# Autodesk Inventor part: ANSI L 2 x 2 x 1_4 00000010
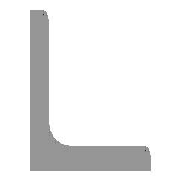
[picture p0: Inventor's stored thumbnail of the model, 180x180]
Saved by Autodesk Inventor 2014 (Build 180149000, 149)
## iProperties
_FrameMemberDoc: Frame Member File
_Version: 15.0.0
_CCFamilyMember: 11
_CCFamilyDisplayName: ANSI L (Equal angles) - Angle Steel
Created: 2007-02
Part Number: ANSI L 2 x 2 x 1_4 00000010
Material: Steel, Mild
Document SubType Name: Modeling
Standard: AISC
Designer: Autodesk, Inc.
Size Designation: L 2 x 2 x 1/4
Stock Number: L 2 x 2 x 1/4
Density: 7.86 g/cm^3
Description: Angle Steel
Standards Organization: ANSI
Language: en-US
Categories: <MemberInstance><Categories><Category DisplayName="Structural Shapes" InternalName="089c4875-fa83-4c05-b084-43b9cc11f5ed" Mnemonic="GRDR"><CategoryParameter Dis
Mass: 5445.94 g
Surface Area: 2281.31 cm^2
Volume: 692.867 cm^3
Appearance: Steel
IsCustomPart: 1
G_L: 47.162 in
G_W: 2.000 in
G_H: 2.000 in
+2283D808-2F1C-4F88-8374-570C52666FBE+CUTDETAIL1: Notch
+7C29D4AB-C23D-49FB-A867-DF174C4492B2+CUTDETAIL2: Cut
+B5C2A3DA-737D-4151-A737-5317CCD108A8+CUTDETAIL3: Notch
+B0BDC58B-F2D9-4CD2-9A0D-96DA2DAF80EC+CUTDETAIL4: Notch
+B47E5654-80DF-4891-BFA1-6A0897AAD3E9+CUTDETAIL5: Notch
Author: Autodesk, Inc.
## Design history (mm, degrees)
node "Start plane"
node "End plane"
sketch "Sketch"
  geometry: L1 (50.8, 0)-(0, 0); L2 (0, 0)-(0, 50.8); L3 (0, 50.8)-(3.302, 50.8); L4 (6.35, 47.752)-(6.35, 12.7); L5 (12.7, 6.35)-(47.752, 6.35); L6 (50.8, 3.302)-(50.8, 0); L7 (0, -11.041)-(0, 31.538); L8 (-11.041, 0)-(31.538, 0); L9 (0, 63.926)-(0, -23.536) reference; L10 (-23.536, 0)-(63.926, 0) reference; A1 r 6.35 centre (12.7, 12.7) between (6.35, 12.7) and (12.7, 6.35); A2 r 3.048 centre (3.302, 47.752) between (6.35, 47.752) and (3.302, 50.8); A3 r 3.048 centre (47.752, 3.302) between (50.8, 3.302) and (47.752, 6.35); 3 further points
  constraints: 16 end point, 6 point on circle, 6 point on line, 6 tangent, 4 parallel, 3 centre point, 2 collinear, 1 equal radius, 1 horizontal, 1 perpendicular
  dimensions: "d0" = 50.8 distance between parallel lines of L6 L2 (= G_H); "d1" = 50.8 distance between parallel lines of L3 L1 (= G_H); "d2" = 6.35 distance between parallel lines of L2 L4 (= G_T); "d3" = 6.35 distance between parallel lines of L1 L5 (= G_T); "d10" = 0 distance between parallel lines of L7 L2 (computed from ex); "d11" = 0 distance between parallel lines of L8 L1 (computed from d10); "d14" = 6.35 radius of A1 (= G_IR); "d15" = 3.048 radius of A2 (= G_ER)
extrude "Body" new body sketch "Sketch" stored distance "d4" = 1197.9024 (= G_L); taper "d5" = 0 deg
node "Driven Length"
  sketch "Sketch7"
    geometry: L1 (0, 0)-(10, 0) reference
    constraints: 2 end point, 1 horizontal
  workplane "Work Plane12"
  sketch "Sketch8"
    geometry: L1 (-2, 0)-(12, 0) reference; L2 (-2, 1197.902)-(12, 1197.902) reference
    dimensions: "d25" = 1197.9024 distance between parallel lines of L1 L2 (derived)
workplane "Work Plane3"
workplane "Work Plane4"
workplane "Work Plane5"
split "Split1"
workplane "Work Plane6"
workplane "Work Plane7"
workplane "Work Plane8"
workplane "Work Plane9"
workplane "Work Plane10"
workplane "Work Plane11"
workplane "Work Plane13"
workplane "Work Plane14"
workplane "Work Plane15"
workplane "Work Plane16"
body "Solid1"
sketch "Sketch_1"
  geometry: L1 (50.8, 0)-(0, 0); L2 (0, 0)-(0, 50.8); L3 (0, 50.8)-(3.302, 50.8); L4 (6.35, 47.752)-(6.35, 12.7); L5 (12.7, 6.35)-(47.752, 6.35); L6 (50.8, 3.302)-(50.8, 0); A1 r 3.048 centre (3.302, 47.752) between (6.35, 47.752) and (3.302, 50.8); A2 r 6.35 centre (12.7, 12.7) between (6.35, 12.7) and (12.7, 6.35); A3 r 3.048 centre (47.752, 3.302) between (50.8, 3.302) and (47.752, 6.35)
  constraints: 12 end point, 6 point on circle, 3 centre point
extrude "Extrusion2" cut sketch "Sketch_1" stored distance "d26" = 3.302; taper "d27" = 0 deg
sketch "Sketch_2"
  geometry: L1 (50.8, 0)-(0, 0); L2 (0, 0)-(0, 50.8); L3 (0, 50.8)-(3.302, 50.8); L4 (6.35, 47.752)-(6.35, 12.7); L5 (12.7, 6.35)-(47.752, 6.35); L6 (50.8, 3.302)-(50.8, 0); A1 r 3.048 centre (3.302, 47.752) between (6.35, 47.752) and (3.302, 50.8); A2 r 6.35 centre (12.7, 12.7) between (6.35, 12.7) and (12.7, 6.35); A3 r 3.048 centre (47.752, 3.302) between (50.8, 3.302) and (47.752, 6.35)
  constraints: 12 end point, 6 point on circle, 3 centre point
extrude "Extrusion3" cut sketch "Sketch_2" stored distance "d28" = 3.302; taper "d29" = 0 deg
sketch "Sketch_3"
  geometry: L1 (50.8, 0)-(0, 0); L2 (0, 0)-(0, 50.8); L3 (0, 50.8)-(3.302, 50.8); L4 (6.35, 47.752)-(6.35, 12.7); L5 (12.7, 6.35)-(47.752, 6.35); L6 (50.8, 3.302)-(50.8, 0); A1 r 3.048 centre (3.302, 47.752) between (6.35, 47.752) and (3.302, 50.8); A2 r 6.35 centre (12.7, 12.7) between (6.35, 12.7) and (12.7, 6.35); A3 r 3.048 centre (47.752, 3.302) between (50.8, 3.302) and (47.752, 6.35)
  constraints: 12 end point, 6 point on circle, 3 centre point
extrude "Extrusion4" cut sketch "Sketch_3" stored distance "d30" = 3.302; taper "d31" = 0 deg
sketch "Sketch_4"
  geometry: L1 (50.8, 0)-(0, 0); L2 (0, 0)-(0, 50.8); L3 (0, 50.8)-(3.302, 50.8); L4 (6.35, 47.752)-(6.35, 12.7); L5 (12.7, 6.35)-(47.752, 6.35); L6 (50.8, 3.302)-(50.8, 0); A1 r 3.048 centre (3.302, 47.752) between (6.35, 47.752) and (3.302, 50.8); A2 r 6.35 centre (12.7, 12.7) between (6.35, 12.7) and (12.7, 6.35); A3 r 3.048 centre (47.752, 3.302) between (50.8, 3.302) and (47.752, 6.35)
  constraints: 12 end point, 6 point on circle, 3 centre point
extrude "Extrusion5" cut sketch "Sketch_4" stored distance "d32" = 3.302; taper "d33" = 0 deg
other parameters: "G_H" = 50.8 [user parameter; used in 2 equation terms], "G_T" = 6.35 [user parameter; used in 2 equation terms], "G_ER" = 3.048 [user parameter; used in 1 equation term], "G_IR" = 6.35 [user parameter; used in 1 equation term], "G_L" = 1197.9024 (= d25) [user parameter; used in 1 equation term], "ex" = 0 [user parameter; used in 1 equation term], "G_OFFSET_START" = 0 [user parameter; used in 1 equation term], "G_OFFSET_END" = -7.26001 [user parameter; used in 1 equation term], "d12" = 0 (computed from G_OFFSET_START), "d13" = 1197.9024 (= G_OFFSET_END + B_L), "B_L" = 1205.16242 [user parameter; used in 1 equation term], "d24" = 90 deg
